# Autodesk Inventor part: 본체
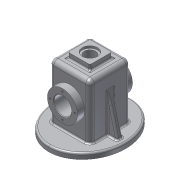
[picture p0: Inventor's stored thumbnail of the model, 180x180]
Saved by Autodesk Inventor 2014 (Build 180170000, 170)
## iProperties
Created: 2017-07
Part Number: 본체
Material: Aluminum 6061
Document SubType Name: Modeling
Designer: user
Density: 2.71 g/cm^3
Appearance: Aluminum - Flat
Author: user
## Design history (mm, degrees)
sketch "Sketch1"
  geometry: L1 (0, 0)-(74, 0); L2 (74, 0)-(74, 100); L3 (74, 100)-(0, 100); L4 (0, 100)-(0, 0)
  constraints: 8 end point, 2 parallel, 1 horizontal, 1 perpendicular
  dimensions: "d0" = 74 distance of L1.start L1.end; "d1" = 100 distance of L1.end L2.end
extrude "Extrusion1" new body sketch "Sketch1" distance "d2" = 74; taper "d3" = 0 deg
workplane "Work Plane1"
sketch "Sketch4"
  geometry: L1 (74, 0)-(74, 100) reference; L2 (74, 100)-(0, 100) reference; C1 r 27.5 at (37, 50); 3 further points
  constraints: 2 midpoint, 1 centre point, 1 horizontal alignment, 1 vertical alignment
  dimensions: "d4" = 55 diameter of C1
extrude "Extrusion2" join sketch "Sketch4" stored distance "d5" = 100; taper "d6" = 0 deg
sketch "Sketch7"
  geometry: C1 r 27.5 at (0, 0) reference; C2 r 16 at (0, 0); 1 further point
  constraints: 1 centre point, 1 coincident
  dimensions: "d18" = 32 diameter of C2
extrude "Extrusion4" cut sketch "Sketch7" stored distance "d19" = 10; taper "d20" = 0 deg
sketch "Sketch8" dims "d21" = 45
  geometry: L1 (0, 0)-(0, 22.5); C1 r 27.5 at (0, 0) reference; 2 further points
  constraints: 2 coincident, 2 end point, 1 vertical, 1 vertical alignment, 2 other
hole "Hole1" sketch "Sketch8" at (0, 22.5) diameter "d22" = 3.242; stored, may be unused: countersink angle "d26" = 90 deg, drill point angle "d28" = 118 deg; dims "d23" = 8, "d24" = 4, "d25" = 2, "d27" = 10
pattern_circular "Circular Pattern1" dims angle "d30" = 360 deg
mirror "Mirror1"
sketch "Sketch10"
  geometry: L1 (102, 111.753)-(-28, 111.753); L2 (-28, 111.753)-(-28, -38); L3 (-28, -38)-(102, -38); L4 (102, -38)-(102, 111.753); L5 (74, 0)-(0, 74); L6 (74, 74)-(0, 0); 2 further points; 1 other entity
  constraints: 12 end point, 3 horizontal, 2 parallel, 2 perpendicular, 2 vertical, 1 coincident, 1 midpoint, 2 other
  dimensions: "d32" = 75 distance from line of point (37, 37) L3; "d33" = 65 distance from line of point (37, 37) L4
extrude "Extrusion5" join sketch "Sketch10" distance "d34" = 10; taper "d35" = 0 deg
sketch "Sketch12"
  geometry: L1 (74, -74)-(0, -74) reference; L2 (74, 0)-(74, -74) reference; L3 (57, -57)-(17, -57); L4 (17, -57)-(17, -17); L5 (17, -17)-(57, -17); L6 (57, -17)-(57, -57); L7 (57, -57)-(17, -17); L8 (17, -57)-(57, -17); 5 further points
  constraints: 12 end point, 6 midpoint, 2 parallel, 2 perpendicular, 1 horizontal, 1 horizontal alignment, 1 vertical alignment
  dimensions: "d36" = 40 distance of L3.end L4.end
extrude "Extrusion6" join sketch "Sketch12" distance "d37" = 10; taper "d38" = 0 deg
sketch "Sketch13"
  geometry: L1 (57, -57)-(57, -17) reference; L2 (57, -17)-(17, -17) reference; C1 r 14 at (37, -37); 3 further points
  constraints: 2 midpoint, 1 centre point, 1 horizontal alignment, 1 vertical alignment
  dimensions: "d39" = 28 diameter of C1
extrude "Extrusion7" cut sketch "Sketch13" distance "d40" = 4; taper "d41" = 0 deg
sketch "Sketch14"
  geometry: C1 r 14 at (0, 0) reference; C2 r 10.5 at (0, 0); 1 further point
  constraints: 1 centre point, 1 coincident
  dimensions: "d42" = 21 diameter of C2
extrude "Extrusion8" cut sketch "Sketch14" stored distance "d43" = 4; taper "d44" = 0 deg
sketch "Sketch16"
  geometry: L1 (92, 0)-(74, 72.194); L2 (74, 0)-(74, 100) reference; L3 (102, 0)-(-28, 0) reference; 2 further points
  constraints: 2 end point, 2 point on line, 1 coincident
  dimensions: "d45" = 104 deg angle of L3 L1; "d58" = 10 distance of L3.start point (92, 0)
extrude "Extrusion9" join sketch "Sketch16" stored distance "d46" = 10; taper "d47" = 0 deg
workplane "Work Plane2"
mirror "Mirror2"
fillet "Fillet1" dims "d48" = 3
fillet "Fillet2" dims "d49" = 8
fillet "Fillet3" dims "d50" = 8
fillet "Fillet4" dims "d51" = 3
fillet "Fillet5" dims "d52" = 3
fillet "Fillet6" dims "d53" = 3
fillet "Fillet7" dims "d54" = 3
chamfer "Chamfer1" distance "d55" = 1; stored, may be unused: second distance "d56" = 2, angle "d57" = 45 deg
sketch "Sketch17"
  geometry: 1 further point
body "Solid1"
